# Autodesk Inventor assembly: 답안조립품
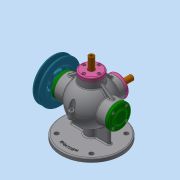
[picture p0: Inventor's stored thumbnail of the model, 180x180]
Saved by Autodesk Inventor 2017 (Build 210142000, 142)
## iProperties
Part Number: 답안조립품
Material: 일반
Document SubType Name: Assembly
Designer: MRC
Author: MRC
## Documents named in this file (17)
- C:\Users\MRC\Desktop\620909V1001\620909V1001\답안조립품.iam
- C:\Users\MRC\Desktop\620909V1001\620909V1001\본체.ipt
- C:\Users\MRC\Desktop\620909V1001\620909V1001\V-벨트풀리.ipt
- C:\Users\MRC\Desktop\620909V1001\620909V1001\너트-M8x1.ipt
- C:\Users\MRC\Desktop\620909V1001\620909V1001\뒤커버.ipt
- C:\Users\MRC\Desktop\620909V1001\620909V1001\베어링- 6202.ipt
- C:\Users\MRC\Desktop\620909V1001\620909V1001\본체커버.ipt
- C:\Users\MRC\Desktop\620909V1001\620909V1001\볼트 M4x0.7.ipt
- C:\Users\MRC\Desktop\620909V1001\620909V1001\슬라이드 커버.ipt
- C:\Users\MRC\Desktop\620909V1001\620909V1001\슬라이드.ipt
- C:\Users\MRC\Desktop\620909V1001\620909V1001\앞커버.ipt
- C:\Users\MRC\Desktop\620909V1001\620909V1001\오일실.ipt
- C:\Users\MRC\Desktop\620909V1001\620909V1001\와셔 8x17.ipt
- C:\Users\MRC\Desktop\620909V1001\620909V1001\축.ipt
- C:\Users\MRC\Desktop\620909V1001\620909V1001\키-4x4.ipt
- C:\Users\MRC\Desktop\620909V1001\620909V1001\스프링.ipt
- C:\Users\MRC\Desktop\620909V1001\620909V1001\스프링2.ipt
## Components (18 placed, 2 different names)
1. V-벨트풀리:1
2. M4x0.7x12:17
3. M4x0.7x12:1
4. M4x0.7x12:3
5. M4x0.7x12:4
6. M4x0.7x12:5
7. M4x0.7x12:2
8. M4x0.7x12:6
9. M4x0.7x12:7
10. M4x0.7x12:8
11. M4x0.7x12:10
12. M4x0.7x12:11
13. M4x0.7x12:12
14. M4x0.7x12:13
15. M4x0.7x12:9
16. M4x0.7x12:14
17. M4x0.7x12:15
18. M4x0.7x12:16
